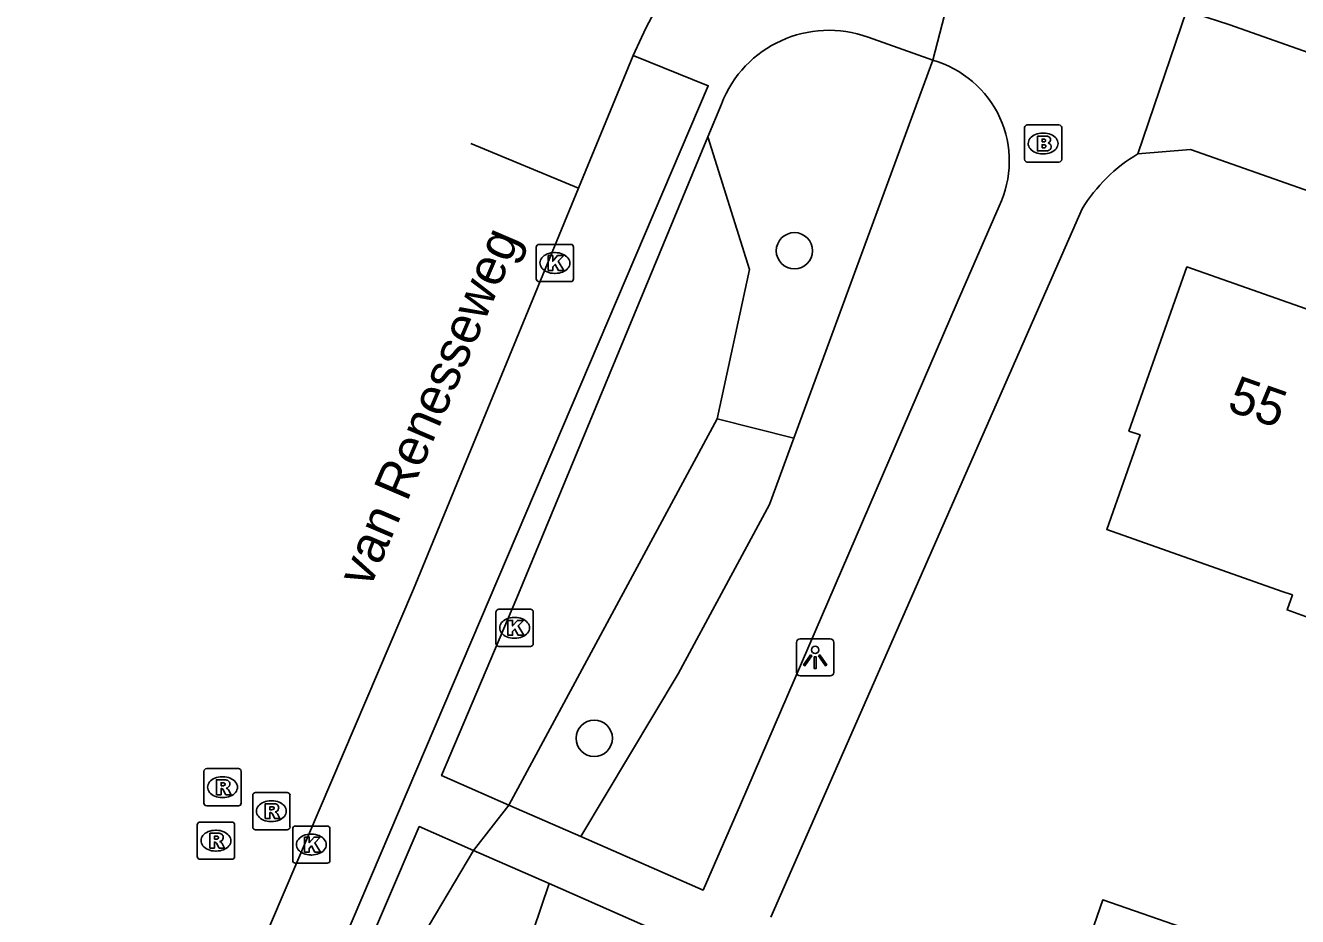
# Model space of a CAD drawing. Extents: x 163268 to 164360, y 381529 to 382285.
# Drawn here: x 163675.73 to 163709.9, y 381848.7 to 381872.66 of the extents above; entities that cross this region are included whole.
import ezdxf

# ---------------------------------------------------------------- set-up
doc = ezdxf.new("R2010")
doc.units = 0
for name, color, linetype in [('IMGEO_Boom', 7, 'Continuous'), ('IMGEO_Brandkraan', 7, 'Continuous'), ('IMGEO_Groenvoorziening', 7, 'Continuous'), ('IMGEO_Kolk', 7, 'Continuous'), ('IMGEO_Lichtpunt', 7, 'Continuous'), ('IMGEO_Openbare_ruimte_label', 7, 'Continuous'), ('IMGEO_Pand', 7, 'Continuous'), ('IMGEO_Pand_nummerreeks', 7, 'Continuous'), ('IMGEO_Rijbaan_lokaal_open', 7, 'Continuous'), ('IMGEO_Rioolput', 7, 'Continuous'), ('IMGEO_Voetpad_open', 7, 'Continuous')]:
    doc.layers.add(name, color=color, linetype=linetype)

msp = doc.modelspace()

# ---------------------------------------------------------------- linework, layer by layer
at = {"layer": 'IMGEO_Boom'}
for centre in [(163696.386, 381866.597), (163691.007, 381853.492)]:
    msp.add_circle(centre, 0.489, dxfattribs=at)
at = {"layer": 'IMGEO_Brandkraan'}
for p, q in [((163702.566, 381869.057), (163702.566, 381869.909)), ((163702.641, 381869.983), (163703.493, 381869.983)), ((163703.054, 381869.763), (163703.079, 381869.763)), ((163703.567, 381869.909), (163703.567, 381869.057)), ((163703.077, 381869.203), (163703.052, 381869.203)), ((163703.493, 381868.983), (163702.641, 381868.983))]:
    msp.add_line(p, q, dxfattribs=at)
for points in [[(163702.566, 381869.057), (163702.566, 381869.909)], [(163702.641, 381869.983), (163703.493, 381869.983)], [(163703.567, 381869.909), (163703.567, 381869.057)], [(163702.914, 381869.683), (163702.914, 381869.283), (163703.127, 381869.283)], [(163703.145, 381869.683), (163702.914, 381869.683)], [(163703.093, 381869.602), (163703.039, 381869.602), (163703.039, 381869.526)], [(163703.039, 381869.526), (163703.092, 381869.526)], [(163703.101, 381869.45), (163703.039, 381869.45), (163703.039, 381869.369)], [(163703.039, 381869.369), (163703.101, 381869.369)], [(163703.493, 381868.983), (163702.641, 381868.983)]]:
    msp.add_lwpolyline(points, dxfattribs=at)
for centre, radius, start, end in [((163702.643, 381869.907), 0.0765, 91.552, 178.448), ((163702.643, 381869.907), 0.0765, 91.552, 178.448), ((163703.491, 381869.907), 0.0765, 1.552, 88.448), ((163703.491, 381869.907), 0.0765, 1.552, 88.448), ((163703.094, 381869.564), 0.0379, 267.8285, 90.9355), ((163703.102, 381869.409), 0.0404, 269.8759, 90.5077), ((163703.149, 381869.538), 0.145, 59.4692, 91.5367), ((163703.174, 381869.585), 0.0922, 285.5137, 58.1501), ((163703.179, 381869.393), 0.105, 301.3115, 78.989), ((163703.133, 381869.534), 0.251, 268.6676, 293.5347), ((163702.643, 381869.059), 0.0765, 181.552, 268.448), ((163702.643, 381869.059), 0.0765, 181.552, 268.448), ((163703.491, 381869.059), 0.0765, 271.552, 358.448), ((163703.491, 381869.059), 0.0765, 271.552, 358.448)]:
    msp.add_arc(centre, radius, start, end, dxfattribs=at)
for centre, major_axis, ratio, start_param, end_param in [((163703.053, 381869.483), (-0.387, 0.002), 0.722429, 4.712389, 7.853982), ((163703.078, 381869.483), (-0.39, 0.002), 0.717154, 1.570796, 4.712389)]:
    msp.add_ellipse(centre, major_axis=major_axis, ratio=ratio, start_param=start_param, end_param=end_param, dxfattribs=at)
at = {"layer": 'IMGEO_Groenvoorziening'}
for points in [[(163696.372, 381861.558), (163700.1, 381871.721)], [(163694.31, 381862.084), (163695.176, 381866.092), (163694.058, 381869.663)], [(163688.714, 381851.696), (163694.31, 381862.084)], [(163696.372, 381861.558), (163694.31, 381862.084)], [(163690.645, 381850.849), (163693.263, 381855.225), (163695.718, 381859.774), (163696.372, 381861.558)], [(163682.956, 381839.425), (163683.48, 381840.099), (163684.779, 381843.059), (163685.718, 381847.03), (163687.763, 381850.477)], [(163689.794, 381849.584), (163689.148, 381847.68), (163686.981, 381841.254), (163685.241, 381837.602)]]:
    msp.add_lwpolyline(points, dxfattribs=at)
at = {"layer": 'IMGEO_Kolk'}
for p, q in [((163689.45, 381865.843), (163689.45, 381866.695)), ((163689.525, 381866.769), (163690.377, 381866.769)), ((163690.451, 381866.695), (163690.451, 381865.843)), ((163689.938, 381866.549), (163689.963, 381866.549)), ((163689.961, 381865.989), (163689.936, 381865.989)), ((163690.377, 381865.769), (163689.525, 381865.769)), ((163688.368, 381856.035), (163688.368, 381856.887)), ((163688.443, 381856.961), (163689.295, 381856.961)), ((163689.369, 381856.887), (163689.369, 381856.035)), ((163688.856, 381856.741), (163688.881, 381856.741)), ((163688.879, 381856.181), (163688.854, 381856.181)), ((163689.295, 381855.961), (163688.443, 381855.961)), ((163682.906, 381850.207), (163682.906, 381851.059)), ((163682.981, 381851.133), (163683.833, 381851.133)), ((163683.907, 381851.059), (163683.907, 381850.207)), ((163683.394, 381850.913), (163683.419, 381850.913)), ((163683.417, 381850.353), (163683.392, 381850.353)), ((163683.833, 381850.133), (163682.981, 381850.133))]:
    msp.add_line(p, q, dxfattribs=at)
for points in [[(163689.45, 381865.843), (163689.45, 381866.695)], [(163689.525, 381866.769), (163690.377, 381866.769)], [(163690.451, 381866.695), (163690.451, 381865.843)], [(163689.771, 381866.469), (163689.894, 381866.469), (163689.894, 381866.318), (163690.024, 381866.469), (163690.188, 381866.469), (163690.042, 381866.318), (163690.195, 381866.069), (163690.043, 381866.069), (163689.958, 381866.233), (163689.894, 381866.166), (163689.894, 381866.069), (163689.771, 381866.069), (163689.771, 381866.469)], [(163690.377, 381865.769), (163689.525, 381865.769)], [(163688.368, 381856.035), (163688.368, 381856.887)], [(163688.443, 381856.961), (163689.295, 381856.961)], [(163689.369, 381856.887), (163689.369, 381856.035)], [(163688.689, 381856.661), (163688.812, 381856.661), (163688.812, 381856.51), (163688.942, 381856.661), (163689.106, 381856.661), (163688.96, 381856.51), (163689.113, 381856.261), (163688.961, 381856.261), (163688.876, 381856.425), (163688.812, 381856.358), (163688.812, 381856.261), (163688.689, 381856.261), (163688.689, 381856.661)], [(163689.295, 381855.961), (163688.443, 381855.961)], [(163682.906, 381850.207), (163682.906, 381851.059)], [(163682.981, 381851.133), (163683.833, 381851.133)], [(163683.907, 381851.059), (163683.907, 381850.207)], [(163683.227, 381850.833), (163683.35, 381850.833), (163683.35, 381850.682), (163683.48, 381850.833), (163683.644, 381850.833), (163683.498, 381850.682), (163683.651, 381850.433), (163683.499, 381850.433), (163683.414, 381850.597), (163683.35, 381850.53), (163683.35, 381850.433), (163683.227, 381850.433), (163683.227, 381850.833)], [(163683.833, 381850.133), (163682.981, 381850.133)]]:
    msp.add_lwpolyline(points, dxfattribs=at)
for centre, start, end in [((163689.527, 381866.693), 91.552, 178.448), ((163689.527, 381866.693), 91.552, 178.448), ((163690.375, 381866.693), 1.552, 88.448), ((163690.375, 381866.693), 1.552, 88.448), ((163689.527, 381865.845), 181.552, 268.448), ((163689.527, 381865.845), 181.552, 268.448), ((163690.375, 381865.845), 271.552, 358.448), ((163690.375, 381865.845), 271.552, 358.448), ((163688.445, 381856.885), 91.552, 178.448), ((163688.445, 381856.885), 91.552, 178.448), ((163689.293, 381856.885), 1.552, 88.448), ((163689.293, 381856.885), 1.552, 88.448), ((163688.445, 381856.037), 181.552, 268.448), ((163688.445, 381856.037), 181.552, 268.448), ((163689.293, 381856.037), 271.552, 358.448), ((163689.293, 381856.037), 271.552, 358.448), ((163682.983, 381851.057), 91.552, 178.448), ((163682.983, 381851.057), 91.552, 178.448), ((163683.831, 381851.057), 1.552, 88.448), ((163683.831, 381851.057), 1.552, 88.448), ((163682.983, 381850.209), 181.552, 268.448), ((163682.983, 381850.209), 181.552, 268.448), ((163683.831, 381850.209), 271.552, 358.448), ((163683.831, 381850.209), 271.552, 358.448)]:
    msp.add_arc(centre, 0.0765, start, end, dxfattribs=at)
for centre, major_axis, ratio, start_param, end_param in [((163689.937, 381866.269), (-0.387, 0.002), 0.722429, 4.712389, 7.853982), ((163689.962, 381866.269), (-0.39, 0.002), 0.717154, 1.570796, 4.712389), ((163688.855, 381856.461), (-0.387, 0.002), 0.722429, 4.712389, 7.853982), ((163688.88, 381856.461), (-0.39, 0.002), 0.717154, 1.570796, 4.712389), ((163683.393, 381850.633), (-0.387, 0.002), 0.722429, 4.712389, 7.853982), ((163683.418, 381850.633), (-0.39, 0.002), 0.717154, 1.570796, 4.712389)]:
    msp.add_ellipse(centre, major_axis=major_axis, ratio=ratio, start_param=start_param, end_param=end_param, dxfattribs=at)
at = {"layer": 'IMGEO_Lichtpunt'}
for p, q in [((163697.346, 381856.164), (163696.538, 381856.164)), ((163697.346, 381856.164), (163696.538, 381856.164)), ((163696.444, 381856.069), (163696.444, 381855.262)), ((163696.444, 381856.069), (163696.444, 381855.262)), ((163697.44, 381855.262), (163697.44, 381856.069)), ((163697.44, 381855.262), (163697.44, 381856.069)), ((163696.538, 381855.168), (163697.346, 381855.168)), ((163696.538, 381855.168), (163697.346, 381855.168))]:
    msp.add_line(p, q, dxfattribs=at)
for points in [[(163696.818, 381855.733), (163696.857, 381855.705), (163696.669, 381855.443), (163696.631, 381855.47), (163696.818, 381855.733)], [(163697.03, 381855.705), (163697.068, 381855.732), (163697.255, 381855.47), (163697.216, 381855.442), (163697.03, 381855.705)], [(163696.92, 381855.685), (163696.967, 381855.685), (163696.967, 381855.363), (163696.92, 381855.363), (163696.92, 381855.685)]]:
    msp.add_lwpolyline(points, dxfattribs=at)
msp.add_circle((163696.943, 381855.867), 0.0994, dxfattribs=at)
for centre, start, end in [((163696.538, 381856.069), 90, 180), ((163696.538, 381856.069), 90, 180), ((163697.346, 381856.069), 0, 90), ((163697.346, 381856.069), 0, 90), ((163696.538, 381855.262), 180, 270), ((163696.538, 381855.262), 180, 270), ((163697.346, 381855.262), 270, 0), ((163697.346, 381855.262), 270, 360)]:
    msp.add_arc(centre, 0.0946, start, end, dxfattribs=at)
at = {"layer": 'IMGEO_Pand'}
for points in [[(163713.01, 381864.02), (163706.929, 381866.163), (163705.373, 381861.75), (163705.67, 381861.645), (163704.774, 381859.103), (163709.49, 381857.441), (163709.762, 381857.345), (163709.62, 381856.942), (163710.415, 381856.662)], [(163707.428, 381848.191), (163704.669, 381849.147), (163703.568, 381845.97)]]:
    msp.add_lwpolyline(points, dxfattribs=at)
at = {"layer": 'IMGEO_Rijbaan_lokaal_open'}
for points in [[(163842.527, 381825.22), (163708.059, 381872.677), (163706.919, 381873.05)], [(163692.05, 381871.848), (163692.281, 381872.333)], [(163690.584, 381868.281), (163692.05, 381871.848)], [(163690.584, 381868.281), (163687.688, 381869.48)], [(163675.727, 381833.061), (163686.152, 381857.502), (163690.584, 381868.281)]]:
    msp.add_lwpolyline(points, dxfattribs=at)
msp.add_arc((163697.688, 381870.009), 5.885, 67.985, 156.7397, dxfattribs=at)
at = {"layer": 'IMGEO_Rioolput'}
for p, q in [((163680.596, 381852.675), (163681.448, 381852.675)), ((163680.521, 381851.749), (163680.521, 381852.601)), ((163681.009, 381852.455), (163681.034, 381852.455)), ((163681.522, 381852.601), (163681.522, 381851.749)), ((163681.908, 381852.033), (163682.76, 381852.033)), ((163681.448, 381851.675), (163680.596, 381851.675)), ((163681.032, 381851.895), (163681.007, 381851.895)), ((163681.833, 381851.107), (163681.833, 381851.959)), ((163682.321, 381851.813), (163682.346, 381851.813)), ((163682.834, 381851.959), (163682.834, 381851.107)), ((163680.344, 381850.313), (163680.344, 381851.165)), ((163680.419, 381851.239), (163681.271, 381851.239)), ((163680.832, 381851.019), (163680.857, 381851.019)), ((163681.345, 381851.165), (163681.345, 381850.313)), ((163682.76, 381851.033), (163681.908, 381851.033)), ((163682.344, 381851.253), (163682.319, 381851.253)), ((163680.855, 381850.459), (163680.83, 381850.459)), ((163681.271, 381850.239), (163680.419, 381850.239))]:
    msp.add_line(p, q, dxfattribs=at)
for points in [[(163680.596, 381852.675), (163681.448, 381852.675)], [(163680.521, 381851.749), (163680.521, 381852.601)], [(163681.11, 381852.373), (163680.858, 381852.375), (163680.858, 381851.975)], [(163681.522, 381852.601), (163681.522, 381851.749)], [(163680.858, 381851.975), (163680.982, 381851.975), (163680.982, 381852.137), (163680.993, 381852.137)], [(163681.036, 381852.294), (163680.982, 381852.294), (163680.982, 381852.213)], [(163680.982, 381852.213), (163681.034, 381852.213)], [(163681.04, 381852.108), (163681.111, 381851.975), (163681.251, 381851.975), (163681.186, 381852.101)], [(163681.908, 381852.033), (163682.76, 381852.033)], [(163681.448, 381851.675), (163680.596, 381851.675)], [(163681.833, 381851.107), (163681.833, 381851.959)], [(163682.422, 381851.731), (163682.17, 381851.733), (163682.17, 381851.333)], [(163682.348, 381851.652), (163682.294, 381851.652), (163682.294, 381851.571)], [(163682.834, 381851.959), (163682.834, 381851.107)], [(163682.17, 381851.333), (163682.294, 381851.333), (163682.294, 381851.495), (163682.305, 381851.495)], [(163682.294, 381851.571), (163682.346, 381851.571)], [(163682.352, 381851.466), (163682.423, 381851.333), (163682.563, 381851.333), (163682.498, 381851.459)], [(163680.344, 381850.313), (163680.344, 381851.165)], [(163680.419, 381851.239), (163681.271, 381851.239)], [(163681.345, 381851.165), (163681.345, 381850.313)], [(163682.76, 381851.033), (163681.908, 381851.033)], [(163680.933, 381850.937), (163680.681, 381850.939), (163680.681, 381850.539)], [(163680.681, 381850.539), (163680.805, 381850.539), (163680.805, 381850.701), (163680.816, 381850.701)], [(163680.859, 381850.858), (163680.805, 381850.858), (163680.805, 381850.777)], [(163680.805, 381850.777), (163680.857, 381850.777)], [(163680.863, 381850.672), (163680.934, 381850.539), (163681.074, 381850.539), (163681.009, 381850.665)], [(163681.271, 381850.239), (163680.419, 381850.239)]]:
    msp.add_lwpolyline(points, dxfattribs=at)
for centre, radius, start, end in [((163680.598, 381852.599), 0.0765, 91.552, 178.448), ((163680.598, 381852.599), 0.0765, 91.552, 178.448), ((163681.446, 381852.599), 0.0765, 1.552, 88.448), ((163681.446, 381852.599), 0.0765, 1.552, 88.448), ((163681.109, 381852.263), 0.109, 350.3612, 89.416), ((163680.992, 381852.084), 0.0533, 26.0293, 88.6989), ((163681.018, 381852.402), 0.19, 274.7715, 282.9687), ((163681.042, 381852.198), 0.0964, 77.0061, 93.1865), ((163681.056, 381852.255), 0.0378, 276.6634, 79.6772), ((163681.107, 381852.263), 0.112, 277.5842, 350.9817), ((163681.091, 381852.048), 0.108, 29.5134, 73.7905), ((163681.91, 381851.957), 0.0765, 91.552, 178.448), ((163681.91, 381851.957), 0.0765, 91.552, 178.448), ((163682.758, 381851.957), 0.0765, 1.552, 88.448), ((163682.758, 381851.957), 0.0765, 1.552, 88.448), ((163680.598, 381851.751), 0.0765, 181.552, 268.448), ((163680.598, 381851.751), 0.0765, 181.552, 268.448), ((163681.446, 381851.751), 0.0765, 271.552, 358.448), ((163681.446, 381851.751), 0.0765, 271.552, 358.448), ((163682.354, 381851.556), 0.0964, 77.0061, 93.1865), ((163682.368, 381851.613), 0.0378, 276.6634, 79.6772), ((163682.421, 381851.621), 0.109, 350.3612, 89.416), ((163682.304, 381851.442), 0.0533, 26.0293, 88.6989), ((163682.33, 381851.76), 0.19, 274.7715, 282.9687), ((163682.419, 381851.621), 0.112, 277.5842, 350.9817), ((163682.403, 381851.406), 0.108, 29.5134, 73.7905), ((163680.421, 381851.163), 0.0765, 91.552, 178.448), ((163680.421, 381851.163), 0.0765, 91.552, 178.448), ((163681.269, 381851.163), 0.0765, 1.552, 88.448), ((163681.269, 381851.163), 0.0765, 1.552, 88.448), ((163681.91, 381851.109), 0.0765, 181.552, 268.448), ((163681.91, 381851.109), 0.0765, 181.552, 268.448), ((163682.758, 381851.109), 0.0765, 271.552, 358.448), ((163682.758, 381851.109), 0.0765, 271.552, 358.448), ((163680.815, 381850.648), 0.0533, 26.0293, 88.6989), ((163680.841, 381850.966), 0.19, 274.7715, 282.9687), ((163680.865, 381850.762), 0.0964, 77.0061, 93.1865), ((163680.879, 381850.819), 0.0378, 276.6634, 79.6772), ((163680.932, 381850.827), 0.109, 350.3612, 89.416), ((163680.93, 381850.827), 0.112, 277.5842, 350.9817), ((163680.914, 381850.612), 0.108, 29.5134, 73.7905), ((163680.421, 381850.315), 0.0765, 181.552, 268.448), ((163680.421, 381850.315), 0.0765, 181.552, 268.448), ((163681.269, 381850.315), 0.0765, 271.552, 358.448), ((163681.269, 381850.315), 0.0765, 271.552, 358.448)]:
    msp.add_arc(centre, radius, start, end, dxfattribs=at)
for centre, major_axis, ratio, start_param, end_param in [((163681.008, 381852.175), (-0.387, 0.002), 0.722429, 4.712389, 7.853982), ((163681.033, 381852.175), (-0.39, 0.002), 0.717154, 1.570796, 4.712389), ((163682.32, 381851.533), (-0.387, 0.002), 0.722429, 4.712389, 7.853982), ((163682.345, 381851.533), (-0.39, 0.002), 0.717154, 1.570796, 4.712389), ((163680.831, 381850.739), (-0.387, 0.002), 0.722429, 4.712389, 7.853982), ((163680.856, 381850.739), (-0.39, 0.002), 0.717154, 1.570796, 4.712389)]:
    msp.add_ellipse(centre, major_axis=major_axis, ratio=ratio, start_param=start_param, end_param=end_param, dxfattribs=at)
at = {"layer": 'IMGEO_Voetpad_open'}
for points in [[(163700.1, 381871.721), (163700.975, 381875.083)], [(163706.919, 381873.05), (163705.615, 381869.206)], [(163698.369, 381872.337), (163700.1, 381871.721)], [(163692.05, 381871.848), (163694.072, 381871.033), (163677.662, 381832.527)], [(163694.058, 381869.663), (163694.422, 381870.542)], [(163694.058, 381869.663), (163688.928, 381857.264), (163686.907, 381852.488), (163688.714, 381851.696)], [(163705.615, 381869.206), (163707.024, 381869.325), (163742.927, 381856.673)], [(163701.885, 381867.794), (163700.757, 381865.208), (163694.935, 381851.713), (163693.932, 381849.408), (163690.645, 381850.849)], [(163695.751, 381848.679), (163704.117, 381867.726)], [(163687.763, 381850.477), (163688.714, 381851.696)], [(163690.645, 381850.849), (163688.714, 381851.696)], [(163687.763, 381850.477), (163686.306, 381851.117), (163680.605, 381837.803), (163679.249, 381834.655)], [(163689.794, 381849.584), (163687.763, 381850.477)], [(163691.751, 381844.348), (163693.31, 381848.039), (163689.794, 381849.584)]]:
    msp.add_lwpolyline(points, dxfattribs=at)
for centre, radius, start, end in [((163697.31, 381869.429), 3.095, 69.9817, 158.9281), ((163699.336, 381869.005), 2.822, 334.5899, 74.298), ((163707.831, 381865.465), 4.348, 120.6406, 148.6668)]:
    msp.add_arc(centre, radius, start, end, dxfattribs=at)

# ---------------------------------------------------------------- texts
at = {"layer": 'IMGEO_Openbare_ruimte_label'}
msp.add_text('van Renesseweg', height=1, rotation=66.7939, dxfattribs=at).set_placement((163684.981, 381857.503))
at = {"layer": 'IMGEO_Pand_nummerreeks'}
msp.add_text('55', height=1, rotation=340.5835, dxfattribs=at).set_placement((163707.975, 381862.316))

doc.saveas('drawing.dxf')
